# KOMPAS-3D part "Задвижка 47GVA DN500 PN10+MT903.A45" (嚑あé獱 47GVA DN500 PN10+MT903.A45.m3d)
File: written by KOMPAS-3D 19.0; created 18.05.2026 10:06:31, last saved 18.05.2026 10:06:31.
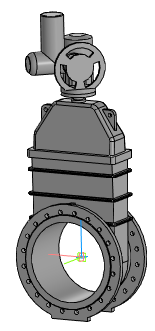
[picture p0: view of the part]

Document properties: Автор: Энергия; Полное имя файла: ..\Задвижка 47GVA DN50_DN1000+MT903.A\Задвижка 47GVA DN500 PN10+MT903.A45.a3d

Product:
- Part/product: Задвижка 47GVA DN500 PN10+MT903.A45
    Масса: 930.268
  - Body: Электропривод МТ903.А45 без блока управления
      Масса: 175.721
  - Body: Задвижка 47GVA DN500 PN10 без исполнительного механизма
      Масса: 754.547

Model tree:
1. Операция без истории:1
2. Операция без истории:2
